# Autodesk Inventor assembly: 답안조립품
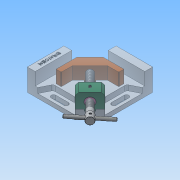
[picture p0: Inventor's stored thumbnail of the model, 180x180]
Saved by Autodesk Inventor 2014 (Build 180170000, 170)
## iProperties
Created: 2019-04
Part Number: 답안조립품
Document SubType Name: Assembly
Designer: net
Author: net
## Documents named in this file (11)
- C:\Users\net\Desktop\490407V1030\답안조립품.iam
- C:\Users\net\Desktop\490407V1030\답안본체.ipt
- C:\Users\net\Desktop\490407V1030\리드스크류.ipt
- C:\Users\net\Desktop\490407V1030\멈춤나사 M4x5.ipt
- C:\Users\net\Desktop\490407V1030\멈춤나사 M4x10.ipt
- C:\Users\net\Desktop\490407V1030\볼트 M4x16.ipt
- C:\Users\net\Desktop\490407V1030\부시.ipt
- C:\Users\net\Desktop\490407V1030\서포트.ipt
- C:\Users\net\Desktop\490407V1030\조.ipt
- C:\Users\net\Desktop\490407V1030\평행 핀 2.5x24.ipt
- C:\Users\net\Desktop\490407V1030\핸들.ipt
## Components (1 placed, 1 different names)
1. 핸들:1
